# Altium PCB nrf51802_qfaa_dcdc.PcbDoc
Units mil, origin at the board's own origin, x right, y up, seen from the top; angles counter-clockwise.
Board outline 584.08 x 642.58 mil, 2 copper layers (Top Layer, Bottom Layer), stack 65.8 mil thick; 22 components, 47 nets, 94 pads, 45 vias.
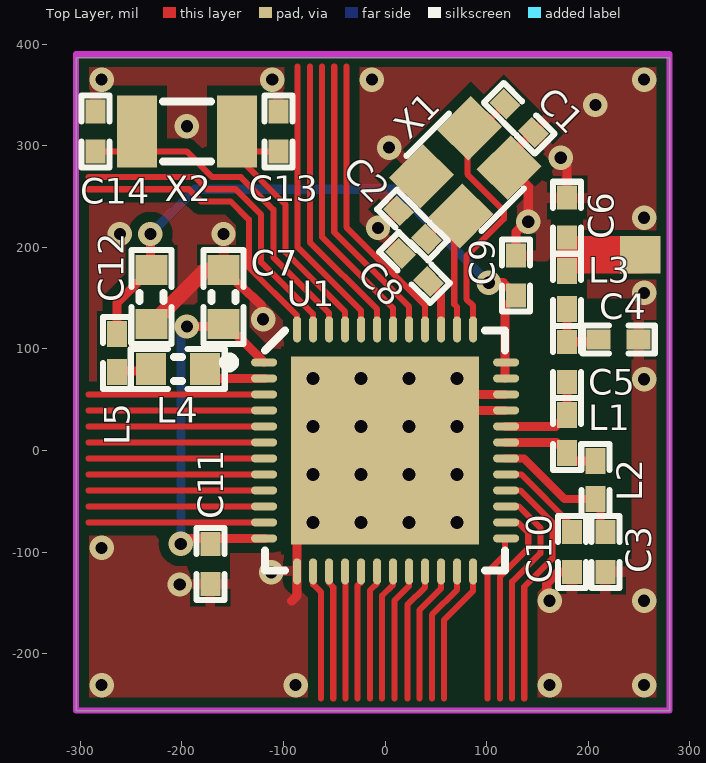
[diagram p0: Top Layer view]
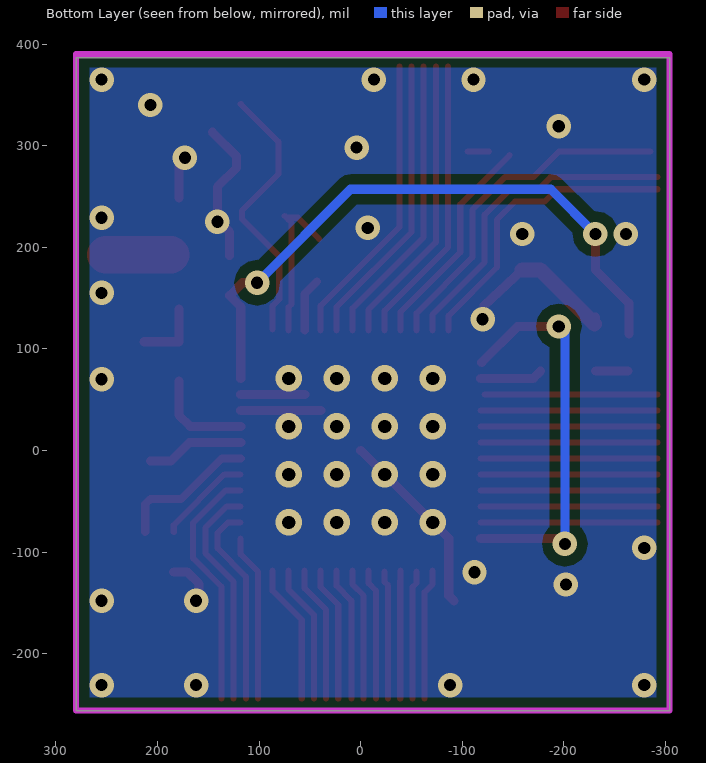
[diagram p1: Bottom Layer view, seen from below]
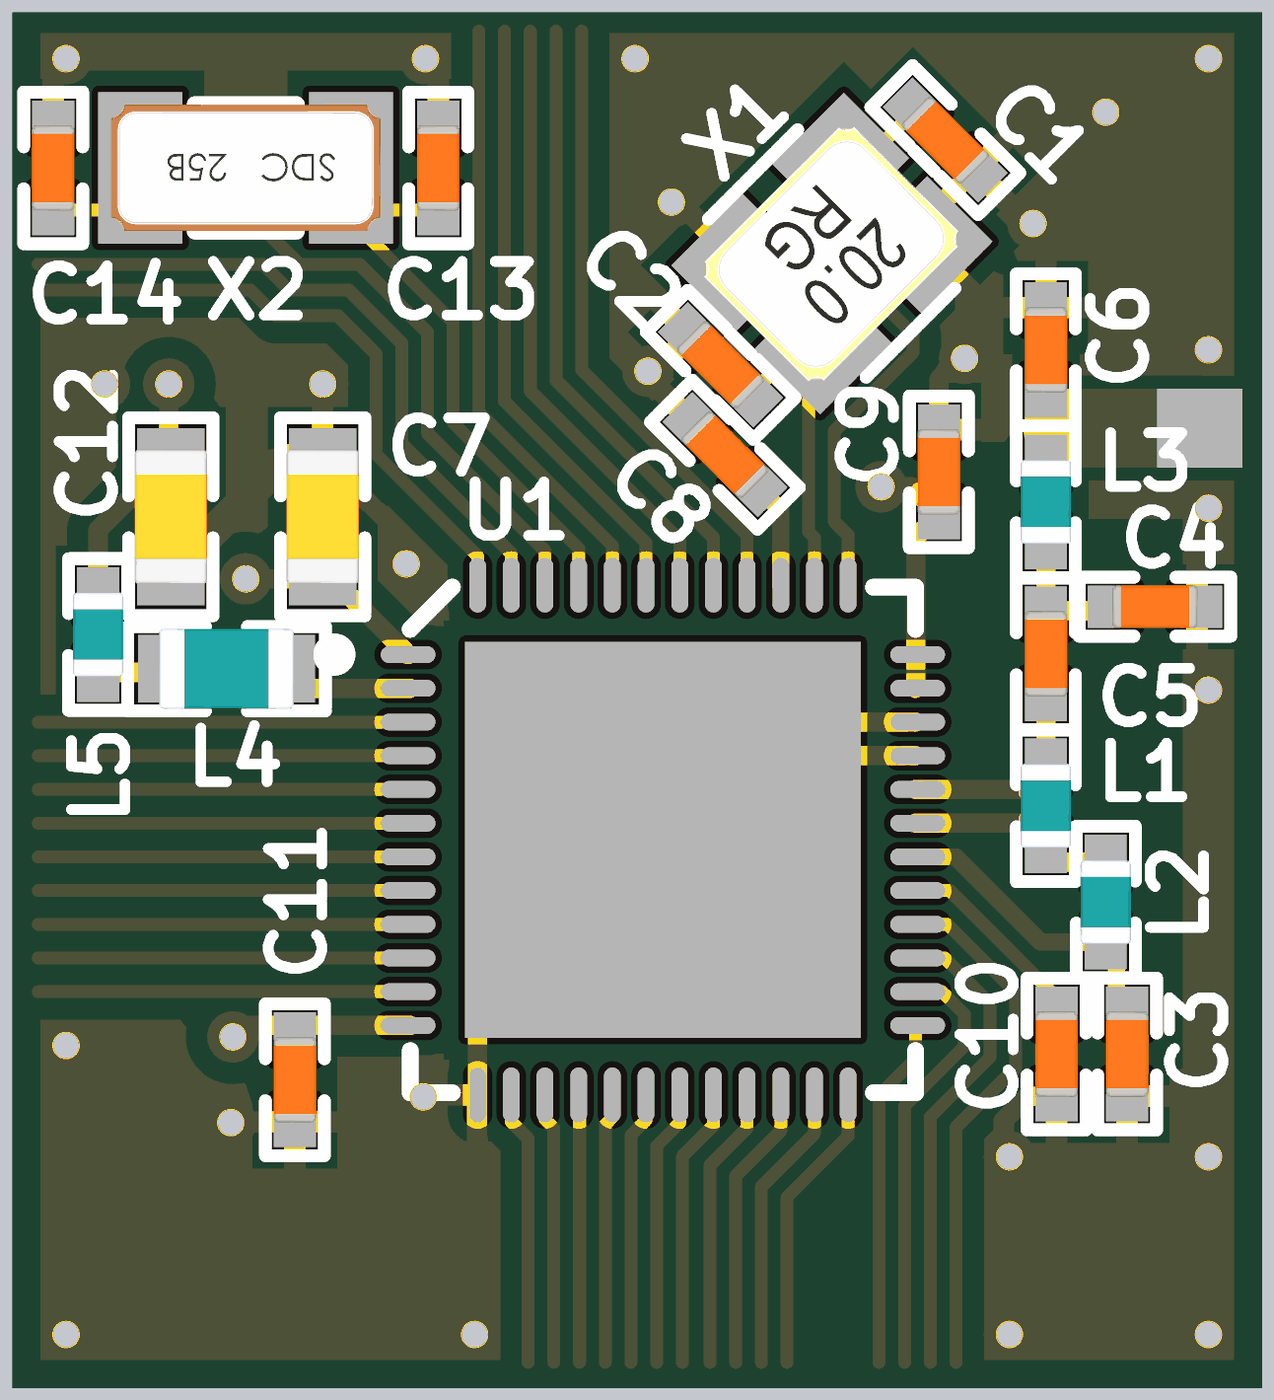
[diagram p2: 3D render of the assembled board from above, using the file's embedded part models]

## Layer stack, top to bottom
Top Solder: solder mask 0.4, Solder Resist, Dk 3.5
Top Layer: signal copper 1.4
Dielectric1: core 63, FR-4, Dk 4.8
Bottom Layer: signal copper 1.4
Bottom Solder: solder mask 0.4, Solder Resist, Dk 3.5

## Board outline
-304.03,-256 280.05,-256 280.05,386.58 -304.03,386.58

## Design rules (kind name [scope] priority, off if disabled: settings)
Clearance Polygon_ANT [(InNamedPolygon('Top_Layer-GND')) or (InNamedPolygon('Bottom_Layer-GND')) vs InNet('NetC6_1')] p1: gap=6
Clearance Polygon [(InNamedPolygon('Top_Layer-GND')) or (InNamedPolygon('Bottom_Layer-GND'))] p2: gap=10
Clearance [All] p3: gap=6
ComponentClearance [All] p1 off: gap=10 collisioncheckmode=3 verticalgap=10 showdistances=FALSE
FabricationTestPointUsage TestPointUsage [All] p1: valid=0 allowmultiple=FALSE
FabricationTestpoint Testpoint [All] p1: side=3 testpointundercomponent=TRUE minsize=40 maxsize=100 preferedsize=60 minholesize=0 maxholesize=40 preferedholesize=32 testpointgrid=1 allowsidetop=TRUE allowsidebottom=TRUE usegrid=TRUE gridtolerance=0.01
Height [All] p1 off: minheight=0 maxheight=1000 prefheight=500
HoleSize [All] p1: absolutevalues=TRUE maxlimit=160 minlimit=12 maxpercent=80.000 minpercent=20.000
MinimumAnnularRing [All] p1 off: minimumring=6
PolygonConnect PolygonConnect_1 [isVia and innet(gnd)] p1: connectstyle=Direct reliefconductorwidth=10 reliefentries=4 polygonreliefangle="90 Angle" airgapwidth=10
PolygonConnect [All] p2: connectstyle=Relief reliefconductorwidth=10 reliefentries=4 polygonreliefangle="90 Angle" airgapwidth=10
RoutingVias [All] p1: holewidth=16 width=32 viastyle="Through Hole" minholewidth=10 minwidth=10 maxholewidth=28 maxwidth=50
SilkToSolderMaskClearance SilkscreenOverComponentPads [IsPad] p1: minsilkscreentomaskgap=10 clearancetoexposedcopper=TRUE
SolderMaskExpansion [All] p1: expansion=3
Width [All] p1: maxlimit=100 minlimit=6 preferedwidth=6
24 further rules are at their usual default settings.

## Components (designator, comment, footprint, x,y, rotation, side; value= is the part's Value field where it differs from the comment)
C1 "12pF" CAPC1005X04L 132,327 r315 top (schematic designator C7)
C2 "12pF" CAPC1005X04L 27,222 r135 top
C3 "2.2nF" CAPC1005X04L 217,-100 r270 top
C4 "0.8pF" CAPC1005X04L 230,109 r0 top
C5 "2.2pF" CAPC1005X04L 179,87 r90 top
C6 "1.5pF" CAPC1005X04L 179,229 r90 top
C7 "4.7µF" CAPC1608X06L -159,151 r90 top (schematic designator C9)
C8 "100nF" CAPC1005X04L 29,180 r135 top (schematic designator C10)
C9 "1.0nF" CAPC1005X04L 129,172 r90 top (schematic designator C8)
C10 "47nF" CAPC1005X04L 184,-100 r270 top (schematic designator C11)
C11 "100nF" CAPC1005X04L -172,-112 r270 top (schematic designator C12)
C12 "1.0µF" CAPC1608X06L -230,151 r90 top (schematic designator C11)
C13 "12pF" CAPC1005X04L -105,314 r270 top
C14 "12pF" CAPC1005X04L -285,314 r270 top
L1 "5.6nH" INDC1005X04L 179,16 r90 top
L2 "10nH" INDC1005X04L 207,-29 r90 top
L3 "3.3nH" INDC1005X04L 179,158 r90 top
L4 "10µH" INDC1608X06L -204,80 r180 top (schematic designator L5)
L5 "15nH" INDC1005X04L -264,96 r90 top (schematic designator L6)
U1 "nRF51802-QFAA" QFN40P600X600X90-48N 0,0 r0 top
X1 "16MHz" BT-XTAL_2520 79,274 r225 top
X2 "32.768kHz" XTAL_3215 -195,314 r180 top

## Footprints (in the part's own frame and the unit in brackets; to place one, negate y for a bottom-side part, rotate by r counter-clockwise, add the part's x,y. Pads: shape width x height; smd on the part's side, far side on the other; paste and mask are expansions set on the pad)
BT-XTAL_2520 [mm] "TSX-2520"
  rect 1.2x1.1 smd: 1(-0.85,-0.7) 2(0.85,-0.7) 3(0.85,0.7) 4(-0.85,0.7)
  silkscreen extent -1.55,-1.33 1.53,1.32, body extent -1.25,-1 1.27,1, height 0.56
CAPC1005X04L [mm] "Chip Capacitor, 2-Leads, Body 1.0x0.5mm, IPC High Density"
  rect 0.6x0.5 smd: 1(-0.5,0) 2(0.5,0)
  silkscreen extent -0.9,-0.35 0.9,0.35, body extent -0.51,-0.25 0.51,0.25, height 0.5
CAPC1608X06L [mm] "Chip Capacitor, 2-Leads, Body 1.6x0.8mm, IPC High Density"
  rect 0.75x0.8 smd: 1(-0.675,0) 2(0.675,0)
  silkscreen extent -1.17,-0.5 1.17,0.5, body extent -0.8,-0.43 0.8,0.43, height 0.8
INDC1005X04L [mm] "Chip Inductor, 2-Leads, Body 1.0x0.5mm, IPC High Density"
  rect 0.65x0.5 smd: 1(-0.475,0) 2(0.475,0)
  silkscreen extent -0.9,-0.35 0.9,0.35, body extent -0.5,-0.3 0.5,0.3, height 0.5
INDC1608X06L [mm] "Chip Inductor, 2-Leads, Body 1.6x0.8mm, IPC High Density"
  rect 0.75x0.8 smd: 1(-0.675,0) 2(0.675,0)
  silkscreen extent -1.17,-0.5 1.17,0.5, body extent -0.8,-0.48 0.8,0.48, height 0.8
QFN40P600X600X90-48N [mm] "QFN, 48-Leads, Body 6,0x6,0mm (max), Pitch 0,40mm, IPC Medium Density"
  oval 0.65x0.2 smd: 1(-3.025,2.2) 2(-3.025,1.8) 3(-3.025,1.4) 4(-3.025,1) 5(-3.025,0.6) 6(-3.025,0.2) 7(-3.025,-0.2) 8(-3.025,-0.6) 9(-3.025,-1) 10(-3.025,-1.4) 11(-3.025,-1.8) 12(-3.025,-2.2) 25(3.025,-2.2) 26(3.025,-1.8) 27(3.025,-1.4) 28(3.025,-1) 29(3.025,-0.6) 30(3.025,-0.2) 31(3.025,0.2) 32(3.025,0.6) 33(3.025,1) 34(3.025,1.4) 35(3.025,1.8) 36(3.025,2.2)
  oval 0.2x0.65 smd: 13(-2.2,-3.025) 14(-1.8,-3.025) 15(-1.4,-3.025) 16(-1,-3.025) 17(-0.6,-3.025) 18(-0.2,-3.025) 19(0.2,-3.025) 20(0.6,-3.025) 21(1,-3.025) 22(1.4,-3.025) 23(1.8,-3.025) 24(2.2,-3.025) 37(2.2,3.025) 38(1.8,3.025) 39(1.4,3.025) 40(1,3.025) 41(0.6,3.025) 42(0.2,3.025) 43(-0.2,3.025) 44(-0.6,3.025) 45(-1,3.025) 46(-1.4,3.025) 47(-1.8,3.025) 48(-2.2,3.025)
  rect 4.7x4.7 smd: 49(0,0)
  silkscreen extent -4.02,-3 3,3, body extent -3,-3 3,3, height 0.9
XTAL_3215 [mm] "XTAL SMD 3.2 x 1.5 mm"
  rect 1x1.8 smd: 1(-1.25,0) 2(1.25,0)
  silkscreen extent -0.6,-0.75 0.6,0.75, body extent -1.6,-0.75 1.6,0.75, height 0.81

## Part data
C1 C2 C13 C14: library part C0402-12p, "Capacitor, NP0, ±2%"
C3: library part C0402-2n2, "Capacitor, X7R, ±10%"
C4: library part C0402-0.8p, "Capacitor, NP0, ±5%"
C5: library part C0402-2.2p, "Capacitor, NP0, ±0.1pF"
C6: library part C0402-1.5p, "Capacitor, NP0, ±0.1pF"
C7: library part C0603-4µ7, "Capacitor, X5R, ±10%"
C8 C11: library part C0402-100n, "Capacitor, X7R, ±10%"
C9: library part C0402-1n0, "Capacitor, X7R, ±10%"
C10: library part C0402-47n, "Capacitor, X7R, ±10%"
C12: library part C0603-1µ0, "Capacitor, X7R, ±10%"
L1: library part L0402-5n6, "High frequency chip inductor ±5%"
L2: library part L0402-10n, "High frequency chip inductor ±5%"
L3: library part L0402-3n3, "High frequency chip inductor ±5%"
L4: library part L0603-10µ, "Chip inductor, IDC,min = 50 mA, ±20%"
L5: library part L0402-15n, "High frequency chip inductor ±10%"
U1: "Multi-protocol Bluetooth Low Energy and 2.4GHz proprietary system-on-chip"
X1: library part XTAL_SMD2520_16MHz_8pF_NDK, "XTAL SMD 2520, 16MHz, 8pF, ±40ppm"
X2: library part "XTAL_FC-135 32.768k", "XTAL SMD 3215, 32.768kHz, 9pF, ±20ppm"

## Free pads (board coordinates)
  rect 40x37 smd: 0(251,192.43)

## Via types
v1: diameter 24, hole 12, Top Layer to Bottom Layer, tented both sides, 29 vias
v2: diameter 25.98, hole 12.99, Top Layer to Bottom Layer, tented both sides, 16 vias

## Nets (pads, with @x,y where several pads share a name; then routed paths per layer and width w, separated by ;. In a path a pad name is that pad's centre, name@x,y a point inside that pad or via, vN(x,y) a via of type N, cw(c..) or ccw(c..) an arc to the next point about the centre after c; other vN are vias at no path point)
AVDD: C9.1 C12.2 L5.2 U1.35 U1.36 | length 619.5
  Top Layer w9: L5.2 -264,145 -231,178 v1(-231,213) ; v1(102,165) 116.31,165 C9.1 118.11,141.43 U1.35@118.11,70.87
  Bottom Layer w9: v1(-231,213) -187,257 10,257 v1(102,165)
GND: C1.2 C2.2 C3.2 C4.2 C6.2 C7.2 C8.2 C9.2 C10.2 C11.2 C12.1 C13.1 C14.1 U1.13 U1.33 U1.34 U1.49 X1.2 X1.4 | length 700.4
  Top Layer w9: C12.1@-231,124 C12.1@-231,131 ; C7.2 -121.5,142.5 ; -91.95,-148.19 -86.61,-142.85 U1.13 ; U1.13@-86.61,-118.11 -86.61,-86.61 U1.49 ; U1.49@39.37,39.37 U1.33@118.11,39.37 ; U1.49@55.12,55.12 U1.34@118.11,55.12 ; C9.2 129,215 139,225 v1(141,225) ; v1@142,225 v1(141,225) ; C1.2 122.15,289.31 X1.4 141,259.33 v1(141,225) ; v1@159,-142 159,-131.33 170.65,-119.68 C10.2 ; C6.2 v1@179,284
  Top Layer w15: C12.1 -176.85,177.58 C7.2
  other v1: -279,-231 -88,-231 162,-231 255,-231 162,-148 255,-148 -202,-132 -112,-120 -279,-96 255,70 -120,129 255,155 -261,213 -159,213 -7,219 255,229 173,288 4,298 -195,319 207,340 -279,365 -111,365 -13,365 255,365
  other v2: -70.87,-70.87 -23.62,-70.87 23.62,-70.87 70.87,-70.87 -70.87,-23.62 -23.62,-23.62 23.62,-23.62 70.87,-23.62 -70.87,23.62 -23.62,23.62 23.62,23.62 70.87,23.62 -70.87,70.87 -23.62,70.87 23.62,70.87 70.87,70.87
NetC1_1: C1.1 U1.37 X1.1 | length 270.1
  Top Layer w6: U1.37 86.61,142.36 80.12,148.85 80.12,191.12 117,228 117,236 81,272 81,303.84 C1.1
NetC2_1: C2.1 U1.38 X1.3 | length 157.4
  Top Layer w6: C2.1 61.84,229 70.87,229 X1.3@70.87,226.89 ; U1.38@70.87,118.11 U1.38 70.87,141.13 68.12,143.88 68.12,224.14 X1.3@70.87,226.89 ; X1.3 X1.3@70.87,226.89
NetC3_1: C3.1 L2.1 U1.30 | length 140.1
  Top Layer w8: U1.30@118.11,-7.87 136.8,-7.87 176.63,-47.7 L2.1 212,-52.7 C3.1@212,-80.31
NetC4_1: C4.1 C5.2 L3.1 | length 66.6
  Top Layer w9: C5.2 L3.1 ; C5.2@179.31,107 C4.1@213.31,107
NetC5_1: C5.1 L1.2 U1.32 | length 99.1
  Top Layer w9: U1.32@118.11,23.62 167.92,23.62 L1.2 C5.1@179,68.3
NetC6_1: C6.1 L3.2 pad.0 | length 64
  Top Layer w37: 187,192.43 pad.0
NetC8_1: C8.1 U1.39 | length 53
  Top Layer w8: C8.1 55.12,153.88 U1.39@55.12,118.11
NetC10_1: C10.1 U1.29 | length 93.4
  Top Layer w6: U1.29@118.11,-23.62 134.17,-23.62 184,-73.45 C10.1
NetL1_1: L1.1 L2.2 U1.31 | length 96.4
  Top Layer w9: U1.31@118.11,7.87 168.43,7.87 186.6,-10.3 L2.2
NetL4_1: L4.1 U1.2 | length 61.8
  Top Layer w9: L4.1@-177,78 -169.87,70.87 U1.2@-118.11,70.87
NetL4_2: L4.2 L5.1 | length 31.7
  Top Layer w9: L5.1@-262.98,78.32 L4.2@-231.32,78.32
P0.00: U1.4 | length 173.9
  Top Layer w6: -292,39.37 U1.4@-118.11,39.37
P0.01: U1.5 | length 173.9
  Top Layer w6: -292,23.62 U1.5@-118.11,23.62
P0.02: U1.6 | length 173.9
  Top Layer w6: -292,7.87 U1.6@-118.11,7.87
P0.03: U1.7 | length 173.9
  Top Layer w6: -292,-7.87 U1.7@-118.11,-7.87
P0.04: U1.8 | length 173.9
  Top Layer w6: -292,-23.62 U1.8@-118.11,-23.62
P0.05: U1.9 | length 173.9
  Top Layer w6: -292,-39.37 U1.9@-118.11,-39.37
P0.06: U1.10 | length 173.9
  Top Layer w6: -292,-55.12 U1.10@-118.11,-55.12
P0.07: U1.11 | length 173.9
  Top Layer w6: -292,-70.87 U1.11@-118.11,-70.87
P0.08: U1.14 | length 129.2
  Top Layer w6: U1.14@-70.87,-118.11 U1.14 -70.87,-131.72 -62.95,-139.64 -62.95,-244
P0.09: U1.15 | length 126.6
  Top Layer w6: U1.15 -55.12,-130.5 -50.95,-134.67 -50.95,-244
P0.10: U1.16 | length 126.1
  Top Layer w6: U1.16@-39.37,-118.11 U1.16 -39.37,-127.77 -38.95,-128.19 -38.95,-244
P0.11: U1.17 | length 126.3
  Top Layer w6: -26.95,-244 -26.95,-132.94 -23.62,-129.6 U1.17
P0.12: U1.18 | length 128.8
  Top Layer w6: -14.95,-244 -14.95,-137.91 -7.87,-130.83 U1.18 U1.18@-7.87,-118.11
P0.13: U1.19 | length 130.3
  Top Layer w6: -2.87,-244 -2.87,-142.8 7.87,-132.06 U1.19 U1.19@7.87,-118.11
P0.14: U1.20 | length 131.9
  Top Layer w6: 9.13,-244 9.13,-147.8 23.62,-133.31 U1.20 U1.20@23.62,-118.11
P0.15: U1.21 | length 133.1
  Top Layer w6: 22.05,-244 22.05,-151.89 39.37,-134.56 U1.21 U1.21@39.37,-118.11
P0.16: U1.22 | length 134.6
  Top Layer w6: 34.05,-244 34.05,-156.89 55.12,-135.82 U1.22 U1.22@55.12,-118.11
P0.17: U1.25 | length 164.5
  Top Layer w6: 101,-244 101,-119.33 118.11,-102.22 U1.25@118.11,-86.61
P0.18: U1.26 | length 201.4
  Top Layer w6: 113,-244 113,-124.3 140.89,-96.41 140.89,-81.26 130.5,-70.87 U1.26@118.11,-70.87
P0.19: U1.27 | length 222.8
  Top Layer w6: U1.27@118.11,-55.12 131.72,-55.12 152.89,-76.29 152.89,-101.38 125,-129.27 125,-244
P0.20: U1.28 | length 244.2
  Top Layer w6: U1.28@118.11,-39.37 132.94,-39.37 164.89,-71.31 164.89,-106.35 137,-134.24 137,-244
P0.21: U1.40 | length 291.8
  Top Layer w6: -38,377.91 -38,219.79 39.37,142.42 U1.40@39.37,118.11
P0.22: U1.41 | length 290.3
  Top Layer w6: -50,377.91 -50,214.82 23.62,141.2 U1.41@23.62,118.11
P0.23: U1.42 | length 288.7
  Top Layer w6: -62,377.91 -62,209.85 7.87,139.98 U1.42@7.87,118.11
P0.24: U1.43 | length 287.2
  Top Layer w6: -74,377.91 -74,204.88 -7.87,138.76 U1.43@-7.87,118.11
P0.25: U1.44 | length 285.6
  Top Layer w6: -86,377.91 -86,199.91 -23.62,137.53 U1.44@-23.62,118.11
P0.28: U1.47 | length 320.4
  Top Layer w6: -292.03,269 -187,269 -175,257 -147.03,257 -122,231.97 -122,185 -70.87,133.87 U1.47@-70.87,118.11
P0.29: U1.48 | length 299
  Top Layer w6: -292.03,257 -193,257 -181,245 -152,245 -134,227 -134,180.03 -86.61,132.64 U1.48@-86.61,118.11
P0.30: U1.3 | length 170
  Top Layer w6: -292,55 U1.3@-122,55
SWCLK: U1.24 | length 137.7
  Top Layer w6: 58.05,-244 58.05,-166.89 86.61,-138.32 U1.24 U1.24@86.61,-118.11
SWDIO: U1.23 | length 136.2
  Top Layer w6: 46.05,-244 46.05,-161.89 70.87,-137.07 U1.23 U1.23@70.87,-118.11
VCC_NRF: C7.1 C11.1 U1.1 U1.12 | length 387.6
  Top Layer w9: v1@-199.61,-86.61 U1.12@-118.11,-86.61 ; v1(-195,122) -154.48,122 U1.1
  Bottom Layer w9: v1@-201,-91 -201,116 v1(-195,122)
  other v1: -201,-92
XL1: C14.2 U1.46 X2.2 | length 340.4
  Top Layer w6: C14.2 -195.31,294.31 -170,269 -142,269 -110,237 -110,189.97 -55.12,135.09 U1.46@-55.12,118.11
XL2: C13.2 U1.45 X2.1 | length 237.9
  Top Layer w6: X2.1@-146.5,290.5 -98,242 -98,194.94 -39.37,136.31 U1.45@-39.37,118.11 ; -126.1,294.31 C13.2

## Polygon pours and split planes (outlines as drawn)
GND on Bottom Layer "Bottom_Layer-GND" (solid, remove dead copper, pour order 1001): -321,400 -321,-266.19 293,-266.19 293,400 -321,400
GND on Top Layer "Top_Layer-GND" (solid, remove dead copper, pour order 5): -333,-278 -333,401.12 -331.7,405.06 302.73,405.06 304.35,410 304.35,-276.03 305,-278

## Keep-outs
Keep-Out Layer:
  lines w6: -304.03,-256 -304.03,390 280.05,390 280.05,-256 -304.03,-256

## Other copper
Top Layer:
  pour cut-out: 98.02,-100 -98,-100 -98,98 97.97,98
  pour cut-out: 53.58,181.42 26.97,154.82 5.05,176.74 31.66,203.34
  pour cut-out: 243,-107 141,-107 141,150 243,150
  pour cut-out: 199,123 125,123 125,186 199,186

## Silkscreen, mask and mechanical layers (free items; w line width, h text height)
Mechanical 1:
  lines w6: -304.03,-256 -304.03,390 280.05,390 280.05,-256 -304.03,-256

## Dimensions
280.05,390 to 280.05,-256 on Mechanical 3
-304.03,-256 to 280.05,-256 on Mechanical 3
